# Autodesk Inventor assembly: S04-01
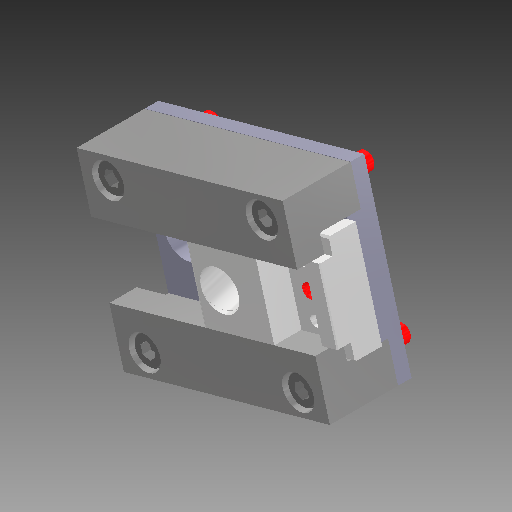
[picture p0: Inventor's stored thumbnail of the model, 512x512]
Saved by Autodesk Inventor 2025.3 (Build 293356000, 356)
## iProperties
Created: 2025-03
Part Number: S04-01
Document SubType Name: Assembly
Designer: Patrik
Stock Number: E 31621_52_30_63
Description: Posuvná jednotka, vsazené vodící lišty
Sending System: KiM GmbH
Major Version: 4.0
Minor Version: 0.0
Format Version: 0.0
Product Id: KiM GmbH
Hersteller: Meusburger
Material: 1.2842
Bestellnummer: E 1265/5
Teilenummer: E 1265/5
Beschreibung: Druckstück gefedert zum Einpressen _ Spring-loaded thrust piece to be pressed in
cc_prop_force_one_body: 1
Author: Patrik
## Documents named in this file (11)
- C:\Users\Patrik\Documents\Skola\Bakalarska prace\Prakticka cast\E 31621_52_30_63.iam
- C:\Users\Patrik\Documents\Skola\Bakalarska prace\Prakticka cast\E 31621_52_30_63.ipt
- C:\Users\Patrik\Documents\Skola\Bakalarska prace\Prakticka cast\E 31621_52_30_63_1.ipt
- C:\Users\Patrik\Documents\Skola\Bakalarska prace\Prakticka cast\E 31621_52_30_63_2.ipt
- C:\Users\Patrik\Documents\Skola\Bakalarska prace\Prakticka cast\E 31621_52_30_63_3.ipt
- C:\Users\Patrik\Documents\Skola\Bakalarska prace\Prakticka cast\E 31621_52_30_63_4.ipt
- C:\Users\Patrik\Documents\Skola\Bakalarska prace\Prakticka cast\E 31621_52_30_63_5.ipt
- C:\Users\Patrik\Documents\Skola\Bakalarska prace\Prakticka cast\E 31621_52_30_63_6.ipt
- C:\Users\Patrik\Documents\Skola\Bakalarska prace\Prakticka cast\E 31621_52_30_63_7.ipt
- C:\Users\Patrik\Documents\Skola\Bakalarska prace\Prakticka cast\E 31621_52_30_63_8.ipt
- C:\Users\Patrik\Documents\Skola\Bakalarska prace\Prakticka cast\E 31621_52_30_63_9.ipt
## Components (12 placed, 10 different names)
1. E 31621_52_30_63_10:1 — Vložit:9
2. E 31621_52_30_63_9:1 — Vložit:11
3. E 31621_52_30_63_8:1 — Vložit:10
4. E 31621_52_30_63_7:1 — Vložit:12
5. E 31621_52_30_63_6:1 — Proti sobě:1, Proti sobě:2, Proti sobě:3
6. E 31621_52_30_63_5:1 — Vložit:5, Vložit:8, Vložit:11, Vložit:12, Proti sobě:2
7. E 31621_52_30_63_4:1 — Vložit:6, Vložit:7, Vložit:9, Vložit:10
8. E 31621_52_30_63_2:2 — Vložit:3
9. E 31621_52_30_63_1:2 — Vložit:4
10. E 31621_52_30_63_3:1 — Vložit:1
11. E 31621_52_30_63_2:1 — Vložit:2
12. E 31621_52_30_63_1:1 — Vložit:1, Vložit:2, Vložit:3, Vložit:4, Vložit:5, Vložit:6, Vložit:7, Vložit:8, Proti sobě:1, Proti sobě:3
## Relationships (15: Insert 12, Mate 3)
- Vložit:1 [Insert]: E 31621_52_30_63_3:1 ↔ E 31621_52_30_63_1:1
- Vložit:2 [Insert]: E 31621_52_30_63_2:1 ↔ E 31621_52_30_63_1:1
- Vložit:3 [Insert]: E 31621_52_30_63_2:2 ↔ E 31621_52_30_63_1:1
- Vložit:4 [Insert]: E 31621_52_30_63_1:2 ↔ E 31621_52_30_63_1:1
- Vložit:5 [Insert]: E 31621_52_30_63_5:1 ↔ E 31621_52_30_63_1:1
- Vložit:6 [Insert]: E 31621_52_30_63_4:1 ↔ E 31621_52_30_63_1:1
- Vložit:7 [Insert]: E 31621_52_30_63_4:1 ↔ E 31621_52_30_63_1:1
- Vložit:8 [Insert]: E 31621_52_30_63_5:1 ↔ E 31621_52_30_63_1:1
- Vložit:9 [Insert]: E 31621_52_30_63_10:1 ↔ E 31621_52_30_63_4:1
- Vložit:10 [Insert]: E 31621_52_30_63_8:1 ↔ E 31621_52_30_63_4:1
- Vložit:11 [Insert]: E 31621_52_30_63_9:1 ↔ E 31621_52_30_63_5:1
- Vložit:12 [Insert]: E 31621_52_30_63_7:1 ↔ E 31621_52_30_63_5:1
- Proti sobě:1 [Mate]: E 31621_52_30_63_6:1 ↔ E 31621_52_30_63_1:1
- Proti sobě:2 [Mate]: E 31621_52_30_63_6:1 ↔ E 31621_52_30_63_5:1
- Proti sobě:3 [Mate]: E 31621_52_30_63_6:1 ↔ E 31621_52_30_63_1:1
